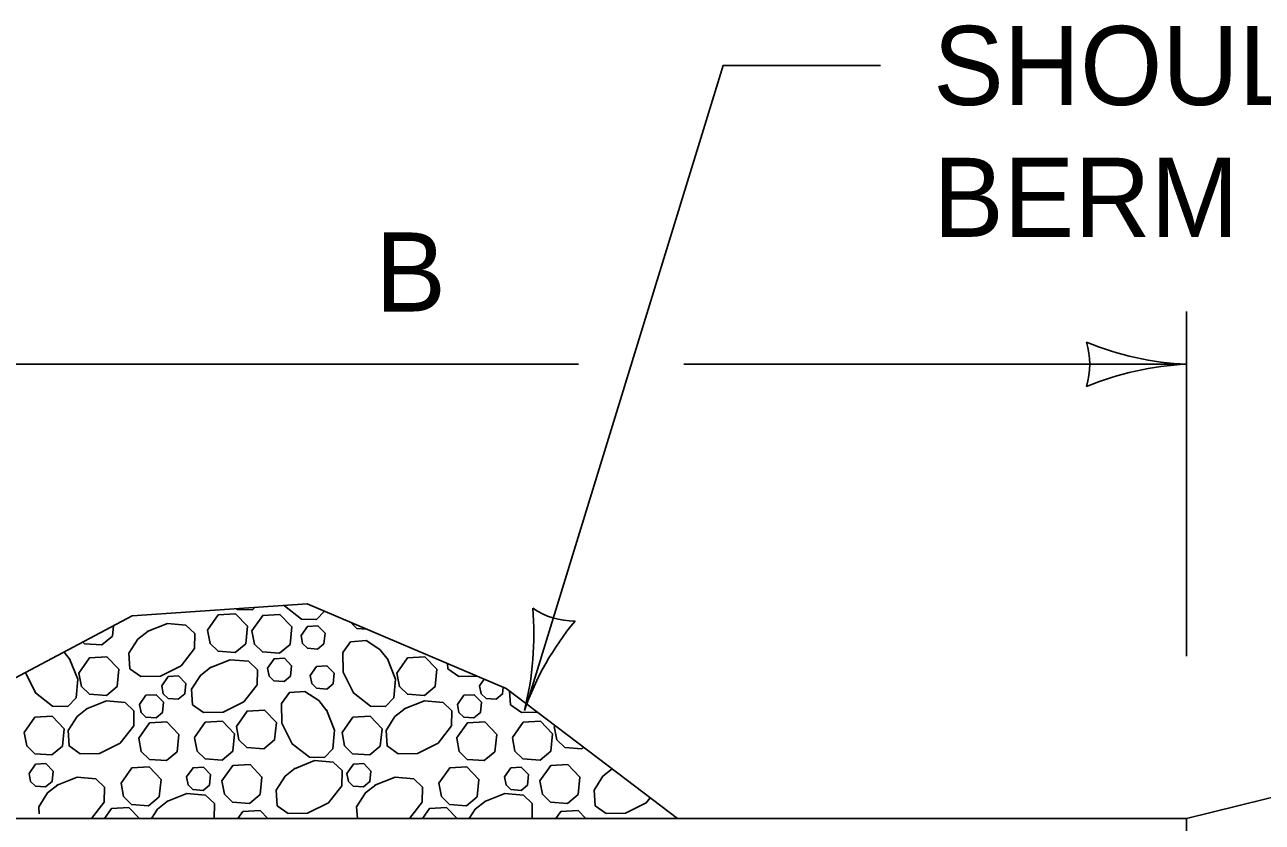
# Model space of a CAD drawing. Extents: x 49991.4 to 50021, y 49987.6 to 50011.4.
# Drawn here: x 50005.238 to 50006.177, y 49992.771 to 49993.376 of the extents above; entities that cross this region are included whole.
import ezdxf

# ---------------------------------------------------------------- set-up
doc = ezdxf.new("R2010")
doc.units = 0
for name, color, linetype in [('Level 1', 7, 'Continuous'), ('Level 2', 7, 'Continuous'), ('Level 3', 7, 'Continuous')]:
    doc.layers.add(name, color=color, linetype=linetype)

msp = doc.modelspace()

# ---------------------------------------------------------------- linework, layer by layer
at = {"layer": 'Level 1'}
for q in [(50006.78605, 49992.94079), (50005.21844, 49992.77409), (50006.11925, 49992.71859)]:
    msp.add_line((50006.11925, 49992.77409), q, dxfattribs=at)
for points in [[(50005.08348, 49992.78657), (50005.18132, 49992.85483), (50005.31912, 49992.92783), (50005.45182, 49992.93703), (50005.60282, 49992.87293), (50005.68767, 49992.80848), (50005.73294, 49992.77409)], [(50005.37624, 49992.91705), (50005.38443, 49992.92871), (50005.39752, 49992.92945), (50005.40661, 49992.92002), (50005.4053, 49992.90681), (50005.39721, 49992.90008), (50005.3843, 49992.90102), (50005.37822, 49992.90691), (50005.37624, 49992.91704)], [(50005.41218, 49992.93429), (50005.41051, 49992.93253), (50005.39908, 49992.93274), (50005.39833, 49992.93333)], [(50005.40995, 49992.91655), (50005.41815, 49992.92821), (50005.43124, 49992.92896), (50005.44034, 49992.91952), (50005.43902, 49992.90631), (50005.43093, 49992.89958), (50005.41801, 49992.90052), (50005.41194, 49992.90642), (50005.40996, 49992.91655)], [(50005.4651, 49992.9314), (50005.45911, 49992.92509), (50005.44768, 49992.9253), (50005.43469, 49992.93547), (50005.4345, 49992.93583)], [(50005.30484, 49992.92027), (50005.30407, 49992.91258), (50005.29599, 49992.90586), (50005.28307, 49992.9068), (50005.28177, 49992.90805)], [(50005.33052, 49992.91598), (50005.34585, 49992.92206), (50005.35994, 49992.92084), (50005.36663, 49992.91448), (50005.36642, 49992.90305), (50005.35625, 49992.89006), (50005.34055, 49992.88221), (50005.32576, 49992.88195), (50005.31742, 49992.88787), (50005.31664, 49992.89966), (50005.3234, 49992.9102), (50005.33113, 49992.91637)], [(50005.44725, 49992.91295), (50005.45216, 49992.91994), (50005.46002, 49992.9204), (50005.46548, 49992.91473), (50005.46468, 49992.90681), (50005.45984, 49992.90277), (50005.45208, 49992.90333), (50005.44843, 49992.90687), (50005.44725, 49992.91295)], [(50005.49704, 49992.91784), (50005.48967, 49992.91837), (50005.48492, 49992.92299)], [(50005.51293, 49992.89526), (50005.51901, 49992.87992), (50005.51779, 49992.86584), (50005.51143, 49992.85914), (50005.5, 49992.85936), (50005.48701, 49992.86952), (50005.47916, 49992.88522), (50005.4789, 49992.90002), (50005.48482, 49992.90834), (50005.49661, 49992.90914), (50005.50715, 49992.90238), (50005.51332, 49992.89463)], [(50005.26744, 49992.90046), (50005.27208, 49992.89463)], [(50005.27168, 49992.89526), (50005.27777, 49992.87992), (50005.27655, 49992.86584), (50005.27019, 49992.85914), (50005.25876, 49992.85936), (50005.24576, 49992.86952), (50005.23808, 49992.8849)], [(50005.27865, 49992.88447), (50005.28685, 49992.89613), (50005.29994, 49992.89687), (50005.30903, 49992.88744), (50005.30772, 49992.87422), (50005.29963, 49992.8675), (50005.28671, 49992.86843), (50005.28063, 49992.87433), (50005.27866, 49992.88447)], [(50005.37808, 49992.88859), (50005.39342, 49992.89467), (50005.4075, 49992.89345), (50005.4142, 49992.88709), (50005.41399, 49992.87566), (50005.40383, 49992.86267), (50005.38812, 49992.85482), (50005.37333, 49992.85456), (50005.365, 49992.86048), (50005.36421, 49992.87227), (50005.37096, 49992.88281), (50005.37871, 49992.88898)], [(50005.42188, 49992.88835), (50005.4268, 49992.89535), (50005.43465, 49992.8958), (50005.44011, 49992.89014), (50005.43932, 49992.8822), (50005.43447, 49992.87817), (50005.42671, 49992.87874), (50005.42307, 49992.88227), (50005.42188, 49992.88835)], [(50005.5199, 49992.88447), (50005.52809, 49992.89613), (50005.54118, 49992.89687), (50005.55028, 49992.88744), (50005.54896, 49992.87422), (50005.54088, 49992.8675), (50005.52795, 49992.86843), (50005.52188, 49992.87433), (50005.5199, 49992.88447)], [(50005.581, 49992.8822), (50005.567, 49992.88195), (50005.55867, 49992.88787), (50005.5584, 49992.89179)], [(50005.34155, 49992.8749), (50005.34647, 49992.8819), (50005.35432, 49992.88234), (50005.35978, 49992.87669), (50005.35899, 49992.86876), (50005.35414, 49992.86472), (50005.34639, 49992.86528), (50005.34274, 49992.86882), (50005.34156, 49992.8749)], [(50005.45416, 49992.88259), (50005.45908, 49992.88958), (50005.46693, 49992.89003), (50005.4724, 49992.88437), (50005.4716, 49992.87644), (50005.46676, 49992.87241), (50005.459, 49992.87297), (50005.45535, 49992.8765), (50005.45417, 49992.88258)], [(50005.58279, 49992.8749), (50005.58633, 49992.87993)], [(50005.60074, 49992.87382), (50005.60023, 49992.86876), (50005.59538, 49992.86472), (50005.58763, 49992.86528), (50005.58398, 49992.86882), (50005.5828, 49992.8749)], [(50005.28438, 49992.85736), (50005.29972, 49992.86343), (50005.3138, 49992.86222), (50005.3205, 49992.85585), (50005.32028, 49992.84442), (50005.31012, 49992.83144), (50005.29442, 49992.82359), (50005.27962, 49992.82332), (50005.27129, 49992.82924), (50005.2705, 49992.84103), (50005.27726, 49992.85157), (50005.285, 49992.85775)], [(50005.32464, 49992.86068), (50005.32956, 49992.86768), (50005.33741, 49992.86812), (50005.34287, 49992.86247), (50005.34208, 49992.85453), (50005.33723, 49992.8505), (50005.32947, 49992.85106), (50005.32583, 49992.8546), (50005.32465, 49992.86068)], [(50005.46655, 49992.85658), (50005.47263, 49992.84125), (50005.47141, 49992.82716), (50005.46505, 49992.82046), (50005.45362, 49992.82068), (50005.44063, 49992.83084), (50005.43278, 49992.84654), (50005.43252, 49992.86134), (50005.43844, 49992.86967), (50005.45023, 49992.87046), (50005.46077, 49992.8637), (50005.46695, 49992.85596)], [(50005.52563, 49992.85736), (50005.54096, 49992.86343), (50005.55505, 49992.86222), (50005.56174, 49992.85585), (50005.56153, 49992.84442), (50005.55136, 49992.83144), (50005.53567, 49992.82359), (50005.52086, 49992.82332), (50005.51254, 49992.82924), (50005.51175, 49992.84103), (50005.51851, 49992.85157), (50005.52625, 49992.85775)], [(50005.56588, 49992.86068), (50005.5708, 49992.86768), (50005.57866, 49992.86812), (50005.58411, 49992.86247), (50005.58332, 49992.85453), (50005.57847, 49992.8505), (50005.57072, 49992.85106), (50005.56707, 49992.8546), (50005.56589, 49992.86068)], [(50005.62673, 49992.85477), (50005.61457, 49992.85456), (50005.60624, 49992.86048), (50005.60555, 49992.87086)], [(50005.39817, 49992.84409), (50005.40636, 49992.85575), (50005.41945, 49992.8565), (50005.42855, 49992.84706), (50005.42724, 49992.83384), (50005.41915, 49992.82712), (50005.40623, 49992.82806), (50005.40015, 49992.83395), (50005.39818, 49992.84409)], [(50005.23711, 49992.83938), (50005.24531, 49992.85104), (50005.2584, 49992.85179), (50005.2675, 49992.84235), (50005.26618, 49992.82914), (50005.2581, 49992.82241), (50005.24517, 49992.82335), (50005.2391, 49992.82924), (50005.23713, 49992.83938)], [(50005.32409, 49992.83506), (50005.33229, 49992.84671), (50005.34538, 49992.84746), (50005.35447, 49992.83803), (50005.35316, 49992.82481), (50005.34507, 49992.81809), (50005.33215, 49992.81903), (50005.32607, 49992.82492), (50005.3241, 49992.83505)], [(50005.36638, 49992.83554), (50005.37458, 49992.84719), (50005.38767, 49992.84794), (50005.39676, 49992.83851), (50005.39545, 49992.82529), (50005.38736, 49992.81857), (50005.37444, 49992.81951), (50005.36836, 49992.8254), (50005.36639, 49992.83553)], [(50005.47836, 49992.83938), (50005.48656, 49992.85104), (50005.49964, 49992.85179), (50005.50874, 49992.84235), (50005.50742, 49992.82914), (50005.49934, 49992.82241), (50005.48642, 49992.82335), (50005.48034, 49992.82924), (50005.47837, 49992.83938)], [(50005.56534, 49992.83506), (50005.57353, 49992.84671), (50005.58662, 49992.84746), (50005.59572, 49992.83803), (50005.5944, 49992.82481), (50005.58632, 49992.81809), (50005.57339, 49992.81903), (50005.56732, 49992.82492), (50005.56535, 49992.83505)], [(50005.60762, 49992.83554), (50005.61582, 49992.84719), (50005.62891, 49992.84794), (50005.63801, 49992.83851), (50005.63669, 49992.82529), (50005.62861, 49992.81857), (50005.61568, 49992.81951), (50005.6096, 49992.8254), (50005.60764, 49992.83553)], [(50005.6617, 49992.82821), (50005.66039, 49992.82712), (50005.64747, 49992.82806), (50005.6414, 49992.83395), (50005.63942, 49992.84409)], [(50005.24085, 49992.8084), (50005.24577, 49992.8154), (50005.25362, 49992.81584), (50005.25908, 49992.81019), (50005.25829, 49992.80226), (50005.25344, 49992.79822), (50005.24569, 49992.79878), (50005.24204, 49992.80232), (50005.24086, 49992.8084)], [(50005.44224, 49992.81201), (50005.45758, 49992.81809), (50005.47166, 49992.81687), (50005.47836, 49992.81051), (50005.47815, 49992.79908), (50005.46799, 49992.78609), (50005.45228, 49992.77824), (50005.43748, 49992.77798), (50005.42916, 49992.7839), (50005.42836, 49992.79568), (50005.43512, 49992.80623), (50005.44287, 49992.8124)], [(50005.48209, 49992.8084), (50005.48701, 49992.8154), (50005.49487, 49992.81584), (50005.50032, 49992.81019), (50005.49954, 49992.80226), (50005.49468, 49992.79822), (50005.48693, 49992.79878), (50005.48328, 49992.80232), (50005.4821, 49992.8084)], [(50005.31065, 49992.80091), (50005.31885, 49992.81258), (50005.33193, 49992.81333), (50005.34103, 49992.80389), (50005.33972, 49992.79067), (50005.33163, 49992.78395), (50005.31871, 49992.78489), (50005.31263, 49992.79078), (50005.31066, 49992.80091)], [(50005.36038, 49992.80571), (50005.3653, 49992.8127), (50005.37315, 49992.81315), (50005.37861, 49992.80749), (50005.37782, 49992.79957), (50005.37298, 49992.79553), (50005.36522, 49992.79609), (50005.36157, 49992.79963), (50005.36039, 49992.80571)], [(50005.38725, 49992.80269), (50005.39544, 49992.81435), (50005.40853, 49992.81509), (50005.41762, 49992.80566), (50005.41631, 49992.79245), (50005.40822, 49992.78572), (50005.39531, 49992.78666), (50005.38922, 49992.79255), (50005.38725, 49992.80269)], [(50005.55189, 49992.80091), (50005.56009, 49992.81258), (50005.57317, 49992.81333), (50005.58228, 49992.80389), (50005.58096, 49992.79067), (50005.57288, 49992.78395), (50005.55995, 49992.78489), (50005.55387, 49992.79078), (50005.5519, 49992.80091)], [(50005.60162, 49992.80571), (50005.60654, 49992.8127), (50005.6144, 49992.81315), (50005.61986, 49992.80749), (50005.61907, 49992.79957), (50005.61422, 49992.79553), (50005.60646, 49992.79609), (50005.60281, 49992.79963), (50005.60163, 49992.80571)], [(50005.62849, 49992.80269), (50005.63668, 49992.81435), (50005.64977, 49992.81509), (50005.65887, 49992.80566), (50005.65755, 49992.79245), (50005.64947, 49992.78572), (50005.63655, 49992.78666), (50005.63046, 49992.79255), (50005.6285, 49992.80269)], [(50005.71218, 49992.78986), (50005.70923, 49992.78609), (50005.69353, 49992.77824), (50005.67873, 49992.77798), (50005.6704, 49992.7839), (50005.66961, 49992.79568), (50005.67637, 49992.80623), (50005.68333, 49992.81178)], [(50005.24858, 49992.77765), (50005.24821, 49992.7831), (50005.25497, 49992.79364), (50005.26271, 49992.79982)], [(50005.26209, 49992.79942), (50005.27742, 49992.8055), (50005.29151, 49992.80429), (50005.2982, 49992.79792), (50005.29799, 49992.78649), (50005.28829, 49992.77409)], [(50005.49006, 49992.77409), (50005.48945, 49992.7831), (50005.49621, 49992.79364), (50005.50395, 49992.79982)], [(50005.50333, 49992.79942), (50005.51866, 49992.8055), (50005.53275, 49992.80429), (50005.53945, 49992.79792), (50005.53923, 49992.78649), (50005.52953, 49992.77409)], [(50005.33369, 49992.77409), (50005.33827, 49992.78124), (50005.34601, 49992.78742)], [(50005.34539, 49992.78703), (50005.36072, 49992.7931), (50005.37481, 49992.79189), (50005.3815, 49992.78552), (50005.38129, 49992.77409)], [(50005.57493, 49992.77409), (50005.57951, 49992.78124), (50005.58726, 49992.78742)], [(50005.58663, 49992.78703), (50005.60197, 49992.7931), (50005.61605, 49992.79189), (50005.62275, 49992.78552), (50005.62253, 49992.77409)], [(50005.29806, 49992.77409), (50005.30343, 49992.78173), (50005.31651, 49992.78248), (50005.3246, 49992.77409)], [(50005.39939, 49992.77409), (50005.40315, 49992.77944), (50005.41624, 49992.78019), (50005.42212, 49992.77409)], [(50005.5393, 49992.77409), (50005.54467, 49992.78173), (50005.55775, 49992.78248), (50005.56584, 49992.77409)], [(50005.64064, 49992.77409), (50005.64439, 49992.77944), (50005.65748, 49992.78019), (50005.66336, 49992.77409)]]:
    msp.add_lwpolyline(points, dxfattribs=at)
at = {"layer": 'Level 3'}
for p, q in [((50005.6185, 49992.86102), (50005.76745, 49993.34541)), ((50005.76735, 49993.34541), (50005.88695, 49993.34541)), ((50006.11925, 49992.96875), (50006.11925, 49993.15879)), ((50005.14648, 49993.11879), (50005.65777, 49993.11879)), ((50005.73777, 49993.11879), (50006.11925, 49993.11879)), ((50006.11925, 49992.89744), (50006.11925, 49992.96875))]:
    msp.add_line(p, q, dxfattribs=at)
for centre, radius, start, end in [((50006.12841, 49993.34093), 0.22232, 247.45601, 267.63952), ((50005.99104, 49993.11879), 0.05477, 342.13882, 17.86118), ((50006.13074, 49992.88608), 0.233, 92.82731, 112.07716), ((50005.39092, 49992.91361), 0.233, 345.73406, 4.98391), ((50005.65441, 49992.97875), 0.05477, 235.04557, 270.76793), ((50005.82636, 49992.78215), 0.22232, 140.36276, 160.54627)]:
    msp.add_arc(centre, radius, start, end, dxfattribs=at)

# ---------------------------------------------------------------- texts
at = {"layer": 'Level 2'}
for s, p in [('SHOULDER', (50005.92695, 49993.31541)), ('BERM', (50005.92695, 49993.21541)), ('B', (50005.50364, 49993.15879))]:
    msp.add_text(s, height=0.06, dxfattribs=at).set_placement(p)

doc.saveas('drawing.dxf')
